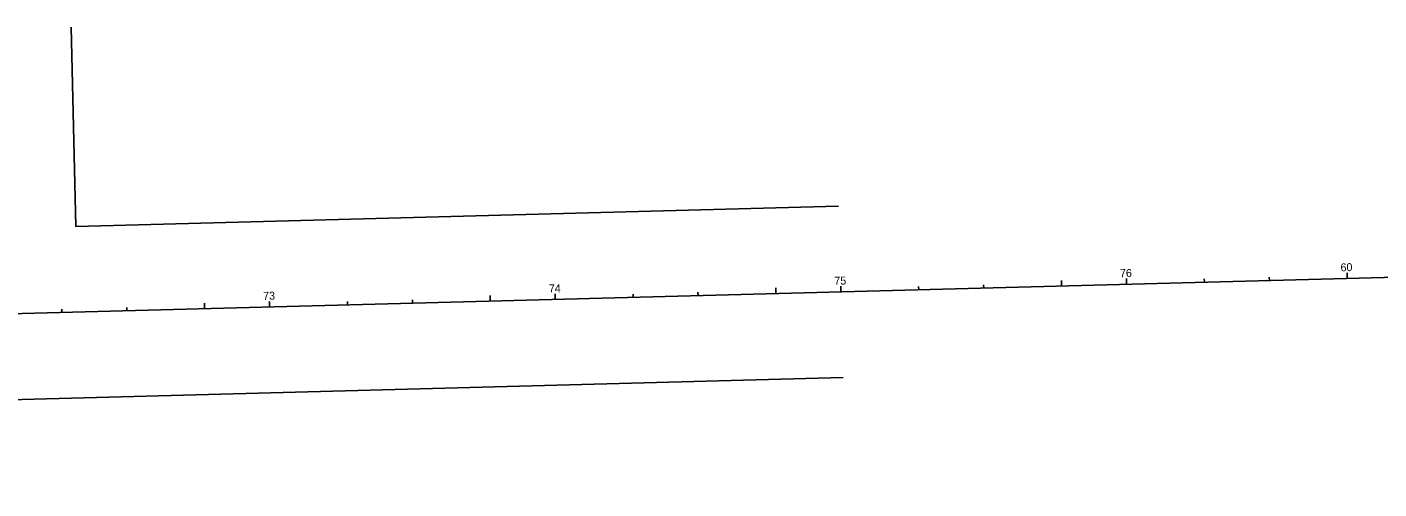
# Model space of a CAD drawing. Extents: x 2402033 to 2407434, y 498266 to 500417.
# Drawn here: x 2404249.1 to 2404722.2, y 498637.4 to 498799 of the extents above; entities that cross this region are included whole.
import ezdxf

# ---------------------------------------------------------------- set-up
doc = ezdxf.new("R2010")
doc.units = 0
for name, color, linetype in [('PV_P_EOP', 7, 'Continuous'), ('PV_P_Shoulder', 7, 'Continuous'), ('RD_P_GR_Lt', 7, 'Continuous'), ('SN_X_Public', 7, 'Continuous'), ('UT_X_Electric_Cells', 7, 'Continuous')]:
    doc.layers.add(name, color=color, linetype=linetype)

msp = doc.modelspace()

# ---------------------------------------------------------------- linework, layer by layer
at = {"layer": 'PV_P_EOP'}
msp.add_line((2403004.47, 498665.82), (2407431.7, 498783.04), dxfattribs=at)
at = {"layer": 'PV_P_Shoulder'}
for p, q in [((2404633.9, 498708.96), (2404633.87, 498710.16)), ((2404711.12, 498711.01), (2404711.07, 498713)), ((2404511.19, 498705.71), (2404511.16, 498706.91)), ((2404533.94, 498706.31), (2404533.88, 498708.31)), ((2404611.16, 498708.36), (2404611.13, 498709.56)), ((2404311.26, 498700.42), (2404311.23, 498701.62)), ((2404334.01, 498701.02), (2404333.98, 498702.22)), ((2404411.23, 498703.07), (2404411.2, 498704.27)), ((2404433.97, 498703.67), (2404433.94, 498704.87))]:
    msp.add_line(p, q, dxfattribs=at)
at = {"layer": 'RD_P_GR_Lt'}
for p, q in [((2404611.16, 498708.36), (2404611.1, 498710.36)), ((2404633.9, 498708.96), (2404633.85, 498710.96)), ((2404661.14, 498709.68), (2404661.11, 498710.88)), ((2404683.88, 498710.28), (2404683.85, 498711.48)), ((2404711.12, 498711.01), (2404711.07, 498713)), ((2404433.97, 498703.67), (2404433.92, 498705.67)), ((2404461.21, 498704.39), (2404461.18, 498705.59)), ((2404483.95, 498704.99), (2404483.92, 498706.19)), ((2404511.19, 498705.71), (2404511.14, 498707.71)), ((2404533.94, 498706.31), (2404533.88, 498708.31)), ((2404561.17, 498707.04), (2404561.14, 498708.24)), ((2404583.92, 498707.64), (2404583.89, 498708.84)), ((2404284.02, 498699.7), (2404283.99, 498700.9)), ((2404311.26, 498700.42), (2404311.21, 498702.42)), ((2404334.01, 498701.02), (2404333.95, 498703.02)), ((2404361.24, 498701.74), (2404361.21, 498702.94)), ((2404383.99, 498702.34), (2404383.96, 498703.54)), ((2404411.23, 498703.07), (2404411.17, 498705.06)), ((2404261.28, 498699.1), (2404261.25, 498700.3))]:
    msp.add_line(p, q, dxfattribs=at)
at = {"layer": 'SN_X_Public'}
for p, q in [((2404711.12, 498711.01), (2404711.07, 498713)), ((2404533.94, 498706.31), (2404533.91, 498707.51))]:
    msp.add_line(p, q, dxfattribs=at)
at = {"layer": 'UT_X_Electric_Cells'}
msp.add_line((2403063.62, 498637.38), (2404534.73, 498676.32), dxfattribs=at)
msp.add_lwpolyline([(2404264.56, 498799), (2404266.22, 498729.24), (2404533.14, 498736.3)], dxfattribs=at)

# ---------------------------------------------------------------- texts
at = {"layer": 'PV_P_Shoulder'}
for s, p in [('60', (2404708.83, 498713.49)), ('75', (2404531.66, 498708.8))]:
    msp.add_text(s, height=2.8, rotation=1.5166, dxfattribs=at).set_placement(p)
at = {"layer": 'RD_P_GR_Lt'}
for s, p in [('75', (2404531.66, 498708.8)), ('76', (2404631.64, 498711.45)), ('73', (2404331.76, 498703.51)), ('74', (2404431.76, 498706.11))]:
    msp.add_text(s, height=2.8, rotation=1.5166, dxfattribs=at).set_placement(p)
at = {"layer": 'SN_X_Public'}
msp.add_text('60', height=2.8, rotation=1.5166, dxfattribs=at).set_placement((2404708.83, 498713.49))

doc.saveas('drawing.dxf')
